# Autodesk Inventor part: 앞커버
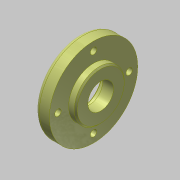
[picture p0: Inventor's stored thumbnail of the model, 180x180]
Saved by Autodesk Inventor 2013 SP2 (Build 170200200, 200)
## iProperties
Created: 2015-12
Part Number: 앞커버
Document SubType Name: Modeling
Designer: mdu
Density: 2.71 g/cm^3
Material: 알루미늄 6061
Mass: 70.9323 g
Surface Area: 93.9278 cm^2
Volume: 26.1743 cm^3
Author: mdu
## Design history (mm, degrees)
sketch "스케치1"
  geometry: L1 (-7.5, 0)-(7.5, 0); L2 (-7.5, 0)-(-7.5, 31); L3 (-7.5, 31)-(2.5, 31); L4 (2.5, 31)-(2.5, 17.5); L5 (2.5, 17.5)-(7.5, 17.5); L6 (7.5, 17.5)-(7.5, 0); 2 further points
  constraints: 12 end point, 3 perpendicular, 1 coincident, 1 horizontal, 1 midpoint, 1 parallel
  dimensions: "d0" = 15 distance of L1.start L1.end; "d1" = 62 diameter of L3 L1; "d2" = 35 diameter of L5 L1; "d5" = 10 distance of L2.end L3.end
revolve "회전1" sketch "스케치1" stored, may be unused: angle "d6" = 90 deg
sketch "스케치2" dims "d42" = 50
  geometry: 3 further points
  constraints: 2 vertical alignment, 1 coincident, 2 other
hole "구멍1" sketch "스케치2" at (0, 25) diameter "d8" = 4.5; stored, may be unused: countersink angle "d12" = 90 deg, drill point angle "d14" = 118 deg; dims "d9" = 6, "d10" = 8, "d11" = 4.4, "d13" = 8
hole "구멍2" diameter "d20" = 18; stored, may be unused: countersink angle "d24" = 90 deg, drill point angle "d26" = 0 deg; dims "d18" = 10, "d19" = 10, "d21" = 6, "d22" = 8, "d23" = 4.4, "d25" = 8
hole "구멍3" diameter "d34" = 30; stored, may be unused: countersink angle "d38" = 90 deg, drill point angle "d40" = 0 deg; dims "d32" = 10, "d33" = 10, "d35" = 6, "d36" = 4, "d37" = 2, "d39" = 7.3
fillet "모깎기1" dims "d27" = 3, "d41" = 0.3
chamfer "모따기1" distance "d29" = 1; stored, may be unused: second distance "d30" = 2, angle "d31" = 45 deg
node "솔리드1"
pattern_circular "원형 패턴1" dims angle "d16" = 360 deg
